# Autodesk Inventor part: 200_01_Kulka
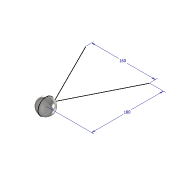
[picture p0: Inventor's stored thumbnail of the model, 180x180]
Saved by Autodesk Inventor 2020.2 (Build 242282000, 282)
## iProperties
Part Number: 200_01_Kulka
Material: Stal
Document SubType Name: Modelowanie
Designer: F.Stasiak
Mass: 263.056 g
Surface Area: 50.2655 cm^2
Volume: 33.5103 cm^3
Density: 7.85 g/cm^3
Appearance: Częściowo polerowany
Catalog Web Link: www.expertbooks.pl
Manager: www.cadconsulting.pl
Company: Fabian Stasiak CAD Consulting
Author: F.Stasiak
Subject: Zbiór ćwiczeń. Autodesk Inventor 2020. Kurs Professional
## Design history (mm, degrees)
sketch "Szkic1"
  geometry: L1 (0, 20)-(0, -20); A1 r 20 centre (0, 0) between (0, 20) and (0, -20); 2 further points
  constraints: 2 coincident, 2 end point, 2 point on circle, 1 centre point, 1 midpoint, 1 vertical
  dimensions: "d0" = 40 diameter of A1
revolve "Obrót1" sketch "Szkic1" stored, may be unused: angle "d1" = 90 deg
sketch "Szkic5"
  geometry: L1 (0, 20)-(-80, 180); L2 (0, 20)-(80, 180); L3 (0, 20)-(0, -20) reference; 1 further point
  constraints: 4 end point, 1 equal length, 1 other
  dimensions: "d7" = 160 distance of L2.end L1.end; "d8" = 180 vertical distance of L2.end point (0, 0)
node "Bryła1"
node "Korpusy bryłowe"
node "Korpusy powierzchniowe"
sketch "Szkic3"
  geometry: C1 r 20 at (0, 0); 1 further point
  constraints: 1 centre point, 1 coincident
